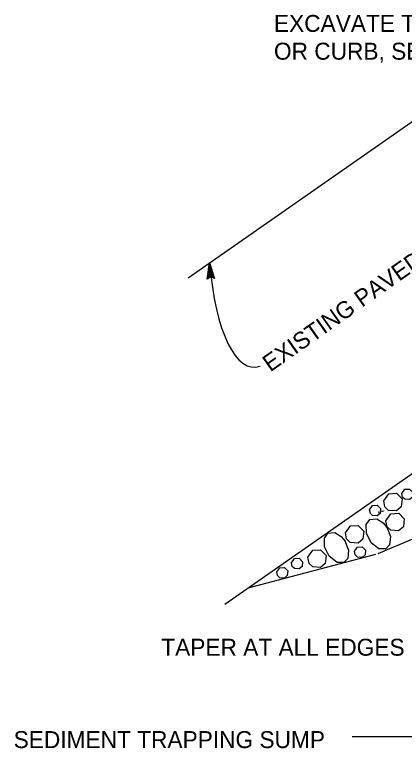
# Model space of a CAD drawing. Extents: x 6709491 to 6710959, y 1869789 to 1870763.
# Drawn here: x 6710377.4 to 6710515.2, y 1870268.5 to 1870528.2 of the extents above; entities that cross this region are included whole.
import ezdxf

# ---------------------------------------------------------------- set-up
doc = ezdxf.new("R2010")
doc.units = 0
for name, color, linetype in [('56 Stg 3 Anno', 7, 'Continuous'), ('57 Undefined', 7, 'Continuous'), ('60 Nongeo Data', 7, 'Continuous')]:
    doc.layers.add(name, color=color, linetype=linetype)

msp = doc.modelspace()

# ---------------------------------------------------------------- linework, layer by layer
at = {"layer": '56 Stg 3 Anno'}
for p, q in [((6710445.56, 1870434.58), (6710446.39, 1870440.42)), ((6710446.39, 1870440.42), (6710446.39, 1870440.42)), ((6710446.39, 1870440.42), (6710448.11, 1870434.78)), ((6710445.88, 1870434.81), (6710446.5, 1870439.1)), ((6710446.21, 1870435.06), (6710446.6, 1870437.78)), ((6710446.5, 1870439.09), (6710447.75, 1870434.98)), ((6710446.6, 1870437.78), (6710447.4, 1870435.12)), ((6710446.78, 1870435.44), (6710445.56, 1870434.58)), ((6710446.53, 1870435.26), (6710446.7, 1870436.45)), ((6710446.7, 1870436.45), (6710447.04, 1870435.32)), ((6710448.11, 1870434.78), (6710446.78, 1870435.44)), ((6710445.56, 1870434.58), (6710445.56, 1870434.58)), ((6710448.11, 1870434.78), (6710448.11, 1870434.78)), ((6710537.79, 1870272.64), (6710496.85, 1870272.64))]:
    msp.add_line(p, q, dxfattribs=at)
msp.add_ellipse((6710463.31, 1870455.68), major_axis=(1.41, 52.24), ratio=0.331, start_param=1.876145, end_param=3.275333, dxfattribs=at)
at = {"layer": '60 Nongeo Data'}
for p, q in [((6710438.76, 1870435.1), (6710545.07, 1870509.22)), ((6710451.72, 1870319.56), (6710722.11, 1870508.07)), ((6710460.47, 1870325.47), (6710505.18, 1870337.2))]:
    msp.add_line(p, q, dxfattribs=at)
for points in [[(6710514.4, 1870358.73), (6710515.44, 1870360.22), (6710517.11, 1870360.31), (6710518.27, 1870359.11), (6710518.1, 1870357.43), (6710517.07, 1870356.57), (6710515.43, 1870356.69), (6710514.65, 1870357.44), (6710514.4, 1870358.73)], [(6710507.98, 1870356.16), (6710509.72, 1870358.64), (6710512.5, 1870358.8), (6710514.43, 1870356.8), (6710514.15, 1870353.99), (6710512.43, 1870352.56), (6710509.69, 1870352.76), (6710508.4, 1870354.01), (6710507.98, 1870356.16)], [(6710502.98, 1870352.99), (6710504.02, 1870354.47), (6710505.69, 1870354.57), (6710506.85, 1870353.37), (6710506.68, 1870351.68), (6710505.65, 1870350.83), (6710504.01, 1870350.95), (6710503.23, 1870351.7), (6710502.98, 1870352.99)], [(6710506.31, 1870351.88), (6710506.21, 1870351.99), (6710506.16, 1870352.2)], [(6710507.19, 1870352.2), (6710507.4, 1870352.51), (6710507.87, 1870352.53), (6710507.93, 1870352.47)], [(6710509, 1870346.77), (6710510.3, 1870343.52), (6710510.04, 1870340.53), (6710508.69, 1870339.11), (6710506.26, 1870339.16), (6710503.51, 1870341.31), (6710501.84, 1870344.64), (6710501.78, 1870347.78), (6710503.04, 1870349.55), (6710505.54, 1870349.72), (6710507.78, 1870348.28), (6710509.09, 1870346.64)], [(6710508.75, 1870349.09), (6710510.49, 1870351.56), (6710513.27, 1870351.72), (6710515.2, 1870349.72), (6710514.92, 1870346.91), (6710513.2, 1870345.49), (6710510.46, 1870345.69), (6710509.17, 1870346.94), (6710508.75, 1870349.09)], [(6710494.41, 1870344.77), (6710496.15, 1870347.24), (6710498.93, 1870347.4), (6710500.86, 1870345.4), (6710500.58, 1870342.59), (6710498.86, 1870341.17), (6710496.12, 1870341.37), (6710494.83, 1870342.62), (6710494.41, 1870344.77)], [(6710494.18, 1870341.96), (6710495.47, 1870338.7), (6710495.22, 1870335.71), (6710493.87, 1870334.29), (6710491.44, 1870334.34), (6710488.68, 1870336.49), (6710487.02, 1870339.83), (6710486.96, 1870342.97), (6710488.22, 1870344.74), (6710490.72, 1870344.9), (6710492.96, 1870343.47), (6710494.27, 1870341.83)], [(6710497.65, 1870338.28), (6710498.69, 1870339.76), (6710500.36, 1870339.86), (6710501.52, 1870338.66), (6710501.35, 1870336.97), (6710500.32, 1870336.12), (6710498.68, 1870336.24), (6710497.9, 1870336.99), (6710497.65, 1870338.28)], [(6710481.12, 1870336.13), (6710482.85, 1870338.61), (6710485.63, 1870338.76), (6710487.56, 1870336.76), (6710487.28, 1870333.96), (6710485.57, 1870332.53), (6710482.83, 1870332.73), (6710481.53, 1870333.98), (6710481.12, 1870336.13)], [(6710475.38, 1870334.21), (6710476.42, 1870335.7), (6710478.09, 1870335.79), (6710479.25, 1870334.59), (6710479.08, 1870332.91), (6710478.05, 1870332.05), (6710476.41, 1870332.17), (6710475.63, 1870332.92), (6710475.38, 1870334.21)], [(6710470.14, 1870330.95), (6710471.19, 1870332.44), (6710472.85, 1870332.53), (6710474.01, 1870331.33), (6710473.84, 1870329.65), (6710472.81, 1870328.79), (6710471.17, 1870328.91), (6710470.39, 1870329.66), (6710470.14, 1870330.95)]]:
    msp.add_lwpolyline(points, dxfattribs=at)
msp.add_spline([(6710505.99, 1870337.51), (6710532.99, 1870347.83), (6710590.83, 1870352.57), (6710625.79, 1870346.13), (6710776.97, 1870278.77)], degree=3, dxfattribs=at)

# ---------------------------------------------------------------- texts
at = {"layer": '57 Undefined'}
for s, p in [('EXCAVATE TO CONFORM TO PAVEMENT ', (6710469.13, 1870522.1)), ('OR CURB, SEE CONFORM DETAIL', (6710469.13, 1870512.26)), ('TAPER AT ALL EDGES', (6710429.28, 1870301.31)), ('SEDIMENT TRAPPING SUMP', (6710377.07, 1870268.62))]:
    msp.add_text(s, height=6, dxfattribs=at).set_placement(p)
msp.add_text('EXISTING PAVED ROADWAY', height=6, rotation=35.1601, dxfattribs=at).set_placement((6710467.83, 1870401.55))

doc.saveas('drawing.dxf')
